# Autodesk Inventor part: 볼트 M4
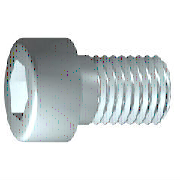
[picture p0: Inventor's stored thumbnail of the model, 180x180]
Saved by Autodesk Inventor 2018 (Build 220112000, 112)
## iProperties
IsCustomPart: 0
Created: 2012-02
Part Number: 볼트 M4
Material: 스테인리스강
Description: 6각 소켓 머리 캡 나사
Document SubType Name: Modeling
Standard: ISO 4762
Designer: mduedu
Standard Revision: Fourth edition 2004-03-01
Standards Organization: ISO
Language: ko-KR
Size Designation: M4 x 10
Categories: <MemberInstance><Categories><Category DisplayName="조임쇠" InternalName="e4da775c-781d-43d5-af7c-5136215cf5a6" Mnemonic="FSTN"><Category DisplayName="볼트" InternalN
Density: 7.75 g/cm^3
Appearance: 반광택
Author: mduedu
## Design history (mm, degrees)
sketch "스케치1"
  geometry: L1 (-1, 0)-(10, 0); L2 (10, 0)-(10, 2); L3 (10, 2)-(1.75, 2); L4 (1.75, 2)-(1.32, 2); L5 (1.32, 2)-(0, 2); L6 (0, 2)-(0, 3.5); L7 (0, 3.5)-(-4, 3.5); L8 (-4, 3.5)-(-4, 1.732); L9 (-4, 1.732)-(-2, 1.732); L10 (-2, 1.732)-(-1, 0); L11 (-6.8, 0)-(12.8, 0) reference; L12 (0, -0.7)-(0, 4.2) reference; L13 (1.75, 2)-(0, 2)
  constraints: 22 end point, 6 parallel, 2 collinear, 2 perpendicular, 1 horizontal, 1 point on line
  dimensions: "d1" = 8.25 distance from line of L3.end L2 (= GEL); "d2" = 0.42952 distance of L4.end L3.end (computed from GAL); "d3" = 4 distance between parallel lines of L8 L6 (= KOH); "d4" = 2 distance of L8.end L9.end (= INTI); "d5" = 60 deg angle of L10 L1; "d6" = 4 diameter of L3 L1 (= GD); "d7" = 4 diameter of L5 L1 (= BDM); "d8" = 3.4641 diameter of L9 L1 (= 1.1547 x SW); "d9" = 7 diameter of L7 L1 (= KOD); "d26" = 10 distance between parallel lines of L12 L2 (= NLG)
revolve "본체" sketch "스케치1" stored, may be unused: angle "d10" = 90 deg
sketch "스케치2"
  geometry: L1 (0, -4.9)-(0, 4.9) reference; L2 (-4.9, 0)-(4.9, 0) reference; L3 (1.732, 0)-(0.866, -1.5); L4 (0.866, -1.5)-(-0.866, -1.5); L5 (-0.866, -1.5)-(-1.732, 0); L6 (-1.732, 0)-(-0.866, 1.5); L7 (-0.866, 1.5)-(0.866, 1.5); L8 (0.866, 1.5)-(1.732, 0); 2 further points
  constraints: 12 end point, 1 coincident, 1 horizontal alignment, 1 point on line, 12 other
extrude "슬롯" join sketch "스케치2" stored distance "d11" = 10; taper "d12" = 0 deg
workplane "Work Plane1"
fillet "Fillet2" dims "d30" = 0.1 (= R)
body "Solid1"
fillet "모깎기1" dims "d17" = 0.4 (= RR)
feature "스레드" dims "d13" = 8.25 (= GEL), "d14" = 0
chamfer "모따기1" distance "d15" = 0.42941 (= -0.5 x SPD + 0.5 x GD); stored, may be unused: second distance "d16" = 0.42941 (= GUL), angle "d27" = 45 deg
other parameters: "GD" = 4 [user parameter; used in 2 equation terms], "NLG" = 10 [user parameter; used in 1 equation term], "GEL" = 8.25 [user parameter; used in 2 equation terms], "KOD" = 7 [user parameter; used in 1 equation term], "KOH" = 4 [user parameter; used in 1 equation term], "INTI" = 2 [user parameter; used in 1 equation term], "GAL" = 0.42941 (= 0.61345 x PTC) [user parameter; used in 1 equation term], "GUL" = 0.42941 (= 0.61345 x PTC) [user parameter; used in 1 equation term], "BDM" = 4 (= NND) [user parameter; used in 1 equation term], "SW" = 3 [user parameter; used in 2 equation terms], "RR" = 0.4 [user parameter; used in 1 equation term], "SPD" = 3.14117 (= NND - 1.2269 x PTC) [user parameter; used in 1 equation term], "d19" = 0, "d28" = 0, "d29" = 0, "R" = 0.1 [user parameter; used in 1 equation term], "TOA" = 30 deg [user parameter], "GD1" = 3.14117 (= THREADDIA - 1.2269 x PTC) [user parameter], "THREADDIA" = 4 [user parameter; used in 1 equation term], "FAWI" = 45 deg [user parameter], "TPU" = 14.28571 (computed from PTC) [user parameter], "PTC" = 0.7 [user parameter; used in 5 equation terms], "NND" = 4 [user parameter; used in 2 equation terms], "E0" = 3.465 (= 1.155 x SW) [user parameter]
